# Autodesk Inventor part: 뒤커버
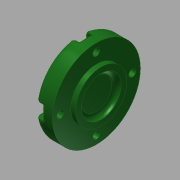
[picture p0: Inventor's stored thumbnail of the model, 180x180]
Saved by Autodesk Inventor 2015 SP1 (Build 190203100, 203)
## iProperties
Created: 2015-11
Part Number: 뒤커버
Material: 알루미늄 6061
Document SubType Name: Modeling
Designer: mduedu
Density: 1 g/cm^3
Appearance: 매끄러움 - 짙은 산림 녹색
Author: mduedu
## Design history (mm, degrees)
sketch "스케치1"
  geometry: L1 (-7, 0)-(7, 0); L2 (-7, 0)-(-7, 27.5); L3 (-7, 27.5)-(4, 27.5); L4 (4, 27.5)-(4, 16); L5 (4, 16)-(7, 16); L6 (7, 16)-(7, 0); 2 further points
  constraints: 12 end point, 3 perpendicular, 2 parallel, 1 coincident, 1 horizontal, 1 midpoint
  dimensions: "d0" = 14 distance of L1.start L1.end; "d1" = 55 diameter of L3 L1; "d2" = 3 distance of L4.end L5.end; "d3" = 32 diameter of L5 L1
revolve "회전1" sketch "스케치1" stored, may be unused: angle "d4" = 90 deg
hole "구멍1" diameter "d7" = 25; stored, may be unused: countersink angle "d11" = 90 deg, drill point angle "d13" = 0 deg; dims "d5" = 10, "d6" = 10, "d8" = 6, "d9" = 4, "d10" = 2, "d12" = 3
fillet "모깎기2" dims "d36" = 3
fillet "모깎기3" dims "d37" = 3
sketch "스케치2" dims "d39" = 45
  geometry: C1 r 12.846 at (0, 0) reference; C2 r 24.5 at (0, 0) reference; 6 further points
  constraints: 2 vertical alignment, 1 coincident, 7 other
  dimensions: "d42" = 360 deg dimension on point (0, 0) point (0, 22.5) (derived)
sketch "스케치3"
  geometry: 8 further points
  constraints: 4 coincident
hole "구멍4" sketch "스케치3" at (-22.5, 0), (0, -22.5), (22.5, 0), (0, 22.5) diameter "d44" = 4.5; stored, may be unused: countersink angle "d48" = 90 deg, drill point angle "d50" = 0 deg; dims "d45" = 6, "d46" = 8, "d47" = 4.6, "d49" = 8
sketch "스케치4"
  geometry: L1 (-4, 0)-(-4, -4.708); L2 (4, 0)-(4, -4.708); A1 r 4 centre (0, 0) between (-4, 0) and (4, 0) reference; A2 r 27.5 centre (0, 22.5) between (-4, -4.708) and (4, -4.708) reference; 3 further points
  constraints: 4 end point, 4 point on circle, 2 tangent, 1 parallel, 1 vertical
extrude "돌출1" cut sketch "스케치4" stored distance "d51" = 0; taper "d52" = 0 deg
fillet "모깎기5" dims "d56" = 0.3
fillet "모깎기6" dims "d57" = 1
node "솔리드1"
pattern_circular "원형 패턴1" dims angle "d54" = 360 deg
